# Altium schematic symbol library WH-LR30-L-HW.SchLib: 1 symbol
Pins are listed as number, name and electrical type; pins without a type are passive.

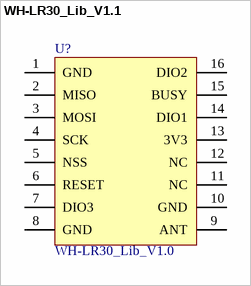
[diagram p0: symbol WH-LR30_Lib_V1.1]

## WH-LR30_Lib_V1.1
designator U?, comment WH-LR30_Lib_V1.0
no: FFA09060900001; id: 2711; yfCode: YF-FFA09060900001; number_goods: 无线通信模块; Value: WH-LR30-H; miaoshu: 常规：不带屏蔽罩; time: 1598422989; types: 可销售; choice: A; currency: C25-104; theory_url_wh: \\192.168.113.192\ad\USR-HW-AD09.SchLib; pcb_url_wh: \\192.168.113.192\ad\USR-HW-AD09.PcbLib
footprint LG30
footprint WH-LR30_Lib_V1.0
footprint L30_I$2F$O_V1.0
footprint L30_I$2F$O_V1.0
footprint L30_I$2F$O_V1.0
footprint L30_I$2F$O_V1.0
pins: 1 GND, 2 MISO, 3 MOSI, 4 SCK, 5 NSS, 6 RESET, 7 DIO3, 8 GND, 9 ANT, 10 GND, 11 NC, 12 NC, 13 3V3, 14 DIO1, 15 BUSY, 16 DIO2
